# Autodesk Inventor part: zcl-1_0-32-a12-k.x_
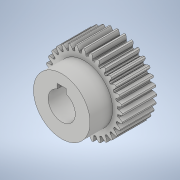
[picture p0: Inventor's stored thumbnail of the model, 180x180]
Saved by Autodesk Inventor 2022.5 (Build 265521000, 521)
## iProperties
Created: 2021-08
Part Number: zcl-1_0-32-a12-k.x_
Material: 一般
Document SubType Name: Modeling
Designer: ImaoCorp
Density: 1 g/cm^3
Appearance: 既定
Sending System: SOLIDWORKS 2019-2019304
MC: AMD64
MC_MODEL: Intel64 Family 6 Model 60 Stepping 3, GenuineIntel
OS: Windows_NT
FRU: Parasolid Version 31.0, build 290,  9- 1-2019
FORMAT: text
GUISE: transmit
KEY: zcl-1_0-32-a12-k
FILE: zcl-1_0-32-a12-k.x_t
DATE: Wed Aug 11 14:58:02 2021
Author: ImaoCorp
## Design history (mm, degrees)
feature "Base1"
node "ソリッド1"
